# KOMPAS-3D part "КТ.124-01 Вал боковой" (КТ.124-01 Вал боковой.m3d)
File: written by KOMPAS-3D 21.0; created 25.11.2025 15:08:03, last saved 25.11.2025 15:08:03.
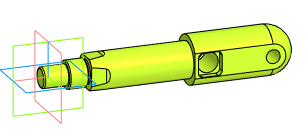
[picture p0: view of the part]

Document properties: Автор: Марсель; Организация: Марсель; Полное имя файла: C:\Users\User\Desktop\Pelorus PRO доработки\ЗАФИКСИРОВАЛИ\Вал боковой\КТ.124-01 Вал боковой.m3d

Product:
- Part/product: КТ.124-01 Вал боковой
    Комментарий: Марсель

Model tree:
1. Операция без истории:1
